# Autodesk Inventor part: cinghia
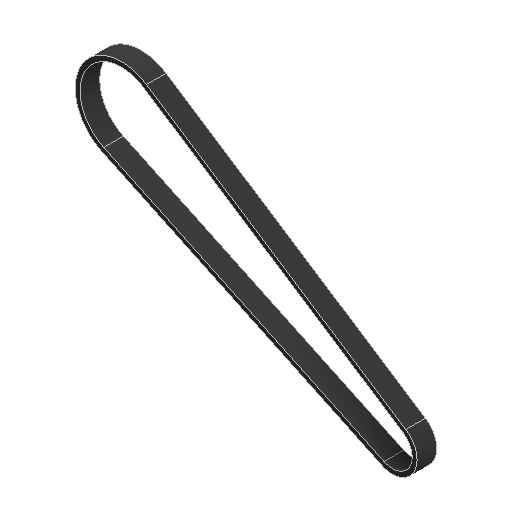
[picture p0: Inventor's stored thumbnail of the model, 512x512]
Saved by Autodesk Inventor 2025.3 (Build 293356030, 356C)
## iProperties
Created: 2025-09
Part Number: cinghia
Material: Gomma
Document SubType Name: Modeling
Designer: R5800u
Density: 0.93 g/cm^3
Appearance: Gomma - Nero
Author: R5800u
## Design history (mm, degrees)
sketch "Schizzo1"
  geometry: L1 (-17.822, -11.311)-(67.446, -51.429); L2 (-5.676, 10.473)-(73.251, -40.957); L3 (-4.857, 11.73)-(74.067, -39.699); L4 (66.807, -52.786)-(-18.46, -12.668); C1 r 13.75 at (-12.5, 0) reference; C2 r 6.384 at (70, -46) reference; A1 r 12.5 centre (-12.5, 0) between (-5.676, 10.473) and (-17.822, -11.311); A2 r 6 centre (70, -46) between (67.446, -51.429) and (73.251, -40.957); A3 r 14 centre (-12.5, 0) between (-4.857, 11.73) and (-18.46, -12.668); A4 r 7.5 centre (70, -46) between (66.807, -52.786) and (74.067, -39.699); 1 further point
  constraints: 8 end point, 8 point on circle, 4 centre point, 3 tangent, 2 coincident, 3 other
  dimensions: "d0" = 25 diameter of A1; "d1" = 12 diameter of A2; "d5" = 1.5 radial gap between concentric circles of A1 A3
extrude "Estrusione1" new body sketch "Schizzo1" distance "d3" = 6; taper "d4" = 0 deg
node "Solido1"
node "Riferimento1"
node "Riferimento2"
